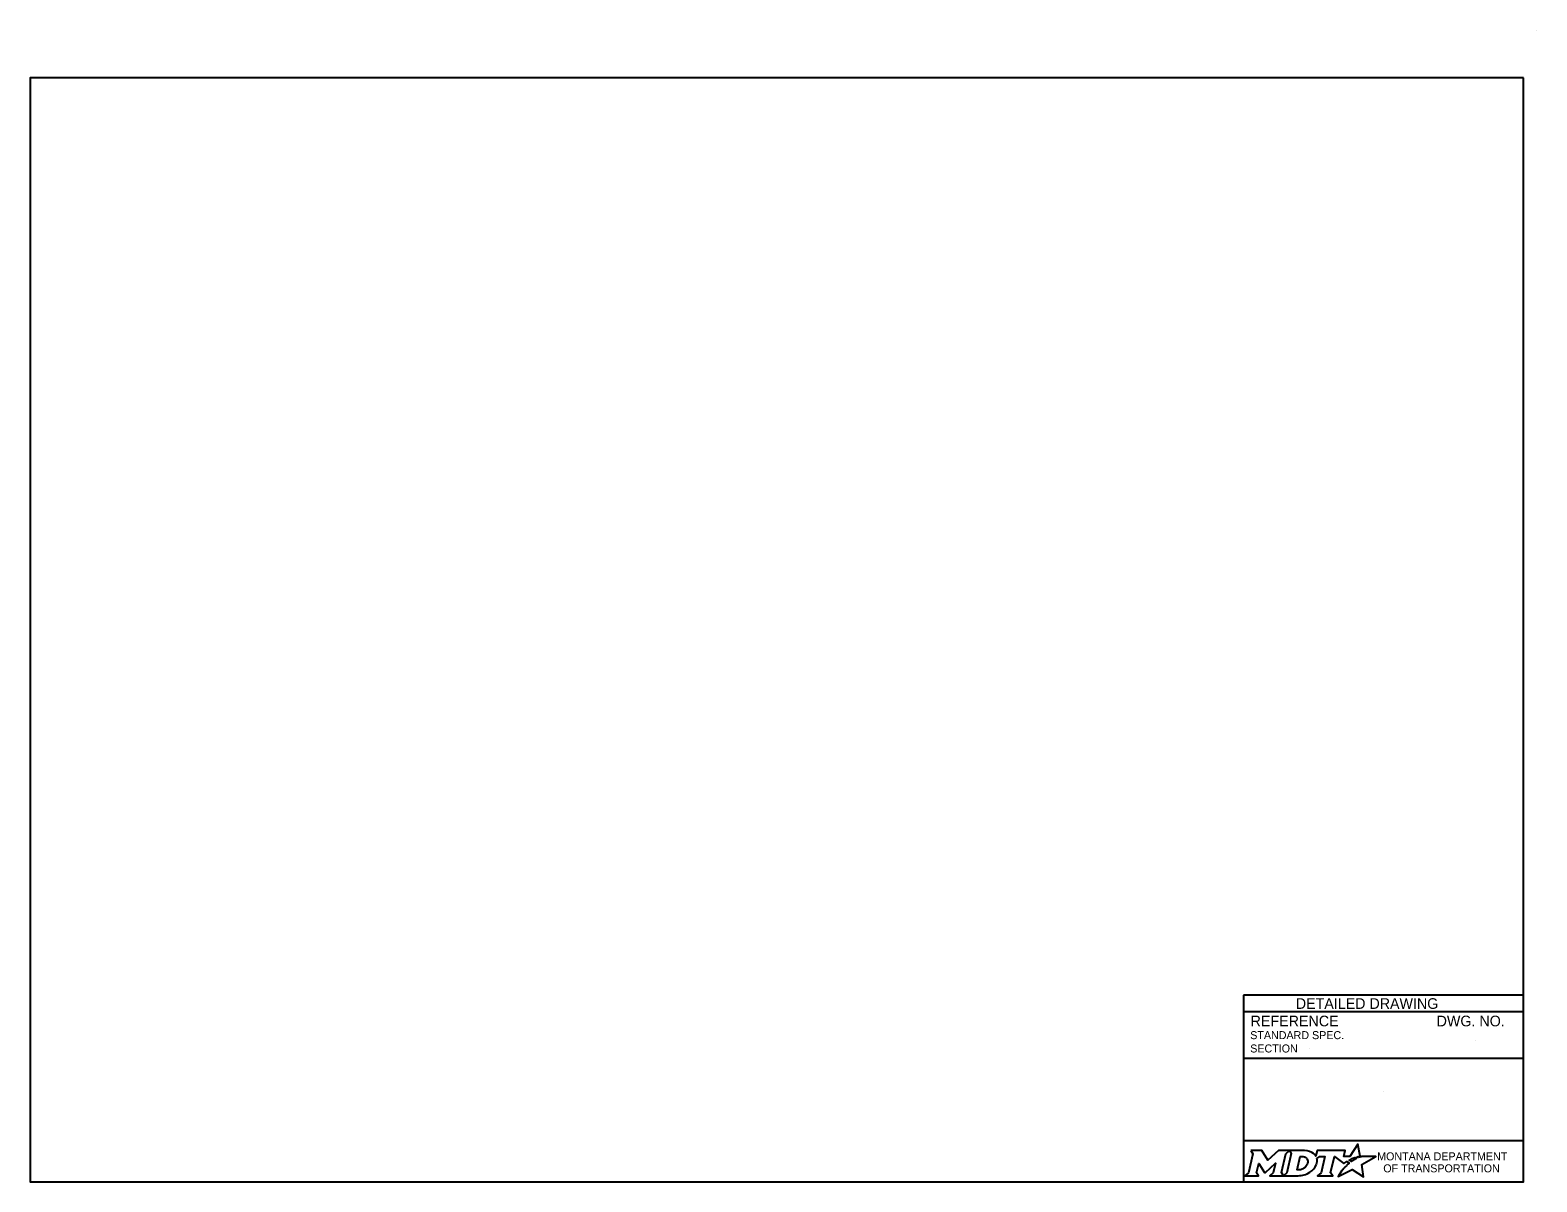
# Model space of a CAD drawing. Extents: x 49987.3 to 50021, y 49987.6 to 50011.4.
# Drawn here: x 50009.74 to 50021.04, y 49999.89 to 50008.52 of the extents above; entities that cross this region are included whole.
import ezdxf

# ---------------------------------------------------------------- set-up
doc = ezdxf.new("R2010")
doc.units = 0
for name, color, linetype in [('Default', 7, 'Continuous'), ('Level 1', 7, 'Continuous'), ('Level 4', 7, 'Continuous')]:
    doc.layers.add(name, color=color, linetype=linetype)

msp = doc.modelspace()

# ---------------------------------------------------------------- linework, layer by layer
at = {"layer": 'Default'}
for points in [[(50019.7, 50000.068), (50019.69, 50000.074), (50019.702, 50000.076), (50019.713, 50000.078), (50019.696, 50000.168), (50019.636, 50000.077), (50019.589, 50000.076), (50019.599, 50000.12), (50019.39, 50000.121), (50019.38, 50000.078), (50019.374, 50000.086)], [(50018.893, 50000.121), (50018.907, 50000.097), (50018.874, 49999.954), (50018.848, 49999.931), (50018.95, 49999.931), (50018.936, 49999.954), (50018.952, 50000.024), (50018.996, 49999.955), (50019.002, 49999.955), (50019.077, 50000.025), (50019.06, 49999.954), (50019.035, 49999.932), (50019.137, 49999.932), (50019.123, 49999.955), (50019.156, 50000.097)], [(50019.156, 50000.097), (50019.182, 50000.121), (50019.099, 50000.121), (50019.02, 50000.048), (50018.975, 50000.12), (50018.893, 50000.121)], [(50019.295, 50000.121), (50019.182, 50000.121), (50019.196, 50000.098), (50019.163, 49999.954), (50019.137, 49999.932), (50019.248, 49999.932)], [(50019.319, 50000.034), (50019.318, 50000.026), (50019.315, 50000.017), (50019.311, 50000.008), (50019.305, 50000.001), (50019.299, 49999.994), (50019.291, 49999.988), (50019.282, 49999.983), (50019.273, 49999.979), (50019.264, 49999.977), (50019.255, 49999.976), (50019.239, 49999.976), (50019.263, 50000.076), (50019.279, 50000.076), (50019.286, 50000.075), (50019.294, 50000.073), (50019.301, 50000.07), (50019.307, 50000.066), (50019.311, 50000.061), (50019.315, 50000.055), (50019.318, 50000.049), (50019.319, 50000.042), (50019.32, 50000.038), (50019.319, 50000.034)], [(50019.387, 50000.062), (50019.411, 50000.075), (50019.448, 50000.075), (50019.42, 49999.954), (50019.392, 49999.931), (50019.508, 49999.931), (50019.491, 49999.954), (50019.52, 50000.075), (50019.591, 50000.023), (50019.612, 50000.038), (50019.632, 50000.027)], [(50019.576, 49999.971), (50019.561, 49999.947), (50019.556, 49999.939), (50019.55, 49999.931), (50019.548, 49999.926), (50019.653, 49999.979), (50019.737, 49999.924), (50019.724, 50000.017), (50019.831, 50000.075), (50019.782, 50000.076), (50019.751, 50000.077), (50019.731, 50000.077), (50019.724, 50000.075), (50019.719, 50000.074), (50019.711, 50000.072), (50019.7, 50000.068)], [(50019.65, 50000.04), (50019.648, 50000.039), (50019.629, 50000.048), (50019.639, 50000.054), (50019.644, 50000.056), (50019.652, 50000.06), (50019.658, 50000.063), (50019.666, 50000.066), (50019.673, 50000.068), (50019.685, 50000.061), (50019.681, 50000.059), (50019.676, 50000.056), (50019.672, 50000.054), (50019.667, 50000.051), (50019.665, 50000.05), (50019.662, 50000.049), (50019.66, 50000.047), (50019.658, 50000.046), (50019.655, 50000.044), (50019.652, 50000.042), (50019.65, 50000.04)], [(50019.293, 49999.939), (50019.302, 49999.942), (50019.315, 49999.947), (50019.335, 49999.958)], [(50019.59, 49999.987), (50019.59, 49999.987)]]:
    msp.add_lwpolyline(points, dxfattribs=at)
for centre, radius, start, end in [((50019.319, 50000.042), 0.0709, 339.5329, 15.8582), ((50019.274, 50000.059), 0.118, 300.9103, 339.1383)]:
    msp.add_arc(centre, radius, start, end, dxfattribs=at)
for centre, major_axis, ratio, start_param, end_param in [((50019.293, 50000.073), (0.0834, -0.0037), 0.568097, 0.61298, 1.570796), ((50019.349, 50000.081), (0.0361, -0.0295), 0.469099, 1.225588, 1.570796), ((50019.621, 50000.017), (-0.0112, -0.0097), 0.021651, 3.157348, 6.283185), ((50019.248, 50000.08), (0, 0.148), 0.987302, 3.139398, 3.456847), ((50019.583, 49999.979), (-0.00694, -0.00806), 0.008222, 0, 3.137361), ((50019.6, 49999.997), (-0.0098, -0.0102), 0.016458, 3.141593, 6.279097)]:
    msp.add_ellipse(centre, major_axis=major_axis, ratio=ratio, start_param=start_param, end_param=end_param, dxfattribs=at)
at = {"layer": 'Level 1'}
msp.add_line((50021.038, 50008.524), (50021.038, 50008.524), dxfattribs=at)
msp.add_lwpolyline([(50020.938, 50008.165), (50009.737, 50008.165), (50009.737, 49999.886), (50020.938, 49999.886)], close=True, dxfattribs=at)
at = {"layer": 'Level 4'}
for p, q in [((50020.938, 50001.286), (50018.838, 50001.286)), ((50018.838, 50001.286), (50018.838, 49999.886)), ((50020.938, 50001.161), (50018.838, 50001.161)), ((50020.574, 50000.946), (50020.574, 50000.946)), ((50020.938, 50000.811), (50018.838, 50000.811)), ((50019.332, 50000.886), (50019.332, 50000.886)), ((50019.888, 50000.562), (50019.888, 50000.562)), ((50020.938, 50000.193), (50018.838, 50000.193))]:
    msp.add_line(p, q, dxfattribs=at)

# ---------------------------------------------------------------- texts
at = {"layer": 'Default'}
for s, p in [('MONTANA DEPARTMENT', (50019.84, 50000.047)), ('OF TRANSPORTATION', (50019.886, 49999.957))]:
    msp.add_text(s, height=0.06, rotation=360, dxfattribs=at).set_placement(p)
at = {"layer": 'Level 4'}
for s, height, p in [('DETAILED DRAWING', 0.0799, (50019.23, 50001.183)), ('REFERENCE', 0.08, (50018.891, 50001.052)), ('DWG. NO.', 0.08, (50020.286, 50001.052)), ('STANDARD SPEC.', 0.06, (50018.888, 50000.956)), ('SECTION', 0.06, (50018.888, 50000.856))]:
    msp.add_text(s, height=height, dxfattribs=at).set_placement(p)

doc.saveas('drawing.dxf')
